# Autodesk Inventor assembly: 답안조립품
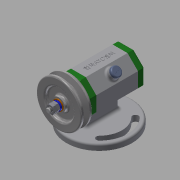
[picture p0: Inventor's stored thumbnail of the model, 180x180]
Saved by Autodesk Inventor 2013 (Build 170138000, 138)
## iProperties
Created: 2017-06
Part Number: 답안조립품
Document SubType Name: Assembly
Designer: Administrator
Author: Administrator
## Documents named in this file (14)
- C:\Users\Administrator\Desktop\470607V1011\답안조립품.iam
- C:\Users\Administrator\Desktop\470607V1011\공용부품\V벨트풀리.ipt
- C:\Users\Administrator\Desktop\470607V1011\공용부품\고무캡.ipt
- C:\Users\Administrator\Desktop\470607V1011\공용부품\너트 M 8.ipt
- C:\Users\Administrator\Desktop\470607V1011\공용부품\뒤커버.ipt
- C:\Users\Administrator\Desktop\470607V1011\공용부품\베어링 15 x 32 x 9.ipt
- C:\Users\Administrator\Desktop\470607V1011\공용부품\볼트 M4 x 12.ipt
- C:\Users\Administrator\Desktop\470607V1011\공용부품\스프링와셔 8.ipt
- C:\Users\Administrator\Desktop\470607V1011\공용부품\앞커버.ipt
- C:\Users\Administrator\Desktop\470607V1011\공용부품\오일 실 15 25 7.ipt
- C:\Users\Administrator\Desktop\470607V1011\공용부품\와셔 8x17.ipt
- C:\Users\Administrator\Desktop\470607V1011\공용부품\축.ipt
- C:\Users\Administrator\Desktop\470607V1011\공용부품\키 3 x 3 x 12.ipt
- C:\Users\Administrator\Desktop\470607V1011\본체.ipt
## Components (2 placed, 2 different names)
1. V벨트풀리:1
2. 고무캡:1
